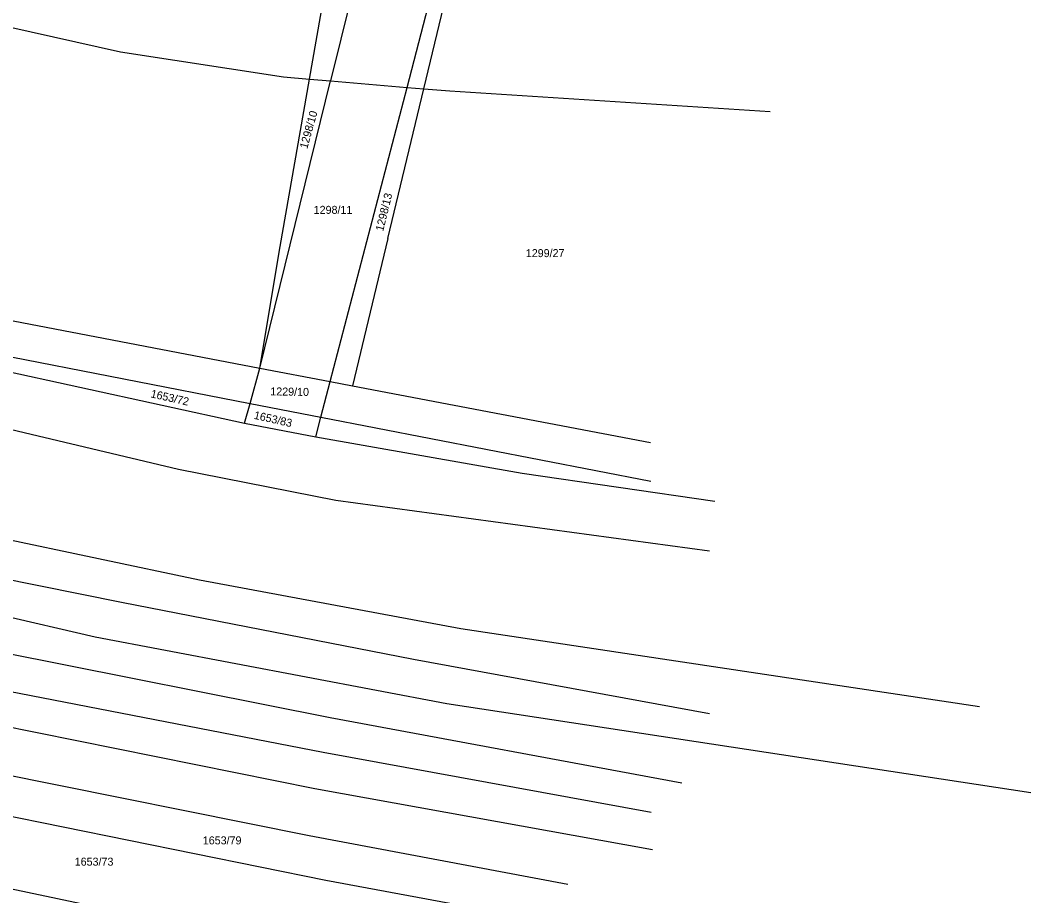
# Model space of a CAD drawing. Extents: x -563148 to -561712, y -1182311 to -1179502.
# Drawn here: x -561979.9 to -561790.5, y -1181327.8 to -1181163.6 of the extents above; entities that cross this region are included whole.
import ezdxf

# ---------------------------------------------------------------- set-up
doc = ezdxf.new("R2010")
doc.units = 0
doc.layers.add('Vrstva 55', color=7, linetype='Continuous')
doc.layers.add('Vrstva 57', color=7, linetype='Continuous')

msp = doc.modelspace()

# ---------------------------------------------------------------- linework, layer by layer
at = {"layer": 'Vrstva 55'}
for p, q in [((-561910.28, -1181129.09), (-561921.71, -1181175.02)), ((-561907.36, -1181176.23), (-561895.44, -1181130.59)), ((-561925.64, -1181174.69), (-561918.1, -1181131.86)), ((-561904.23, -1181176.49), (-561899.45, -1181156.54)), ((-561982, -1181164.87), (-561961.08, -1181169.57)), ((-561961.08, -1181169.57), (-561930.49, -1181174.28)), ((-561930.49, -1181174.28), (-561925.64, -1181174.69)), ((-561934.93, -1181228.84), (-561921.71, -1181175.02)), ((-561931.16, -1181206.06), (-561925.64, -1181174.69)), ((-561925.64, -1181174.69), (-561921.71, -1181175.02)), ((-561921.75, -1181231.35), (-561907.36, -1181176.23)), ((-561921.71, -1181175.02), (-561907.36, -1181176.23)), ((-561910.96, -1181204.59), (-561904.23, -1181176.49)), ((-561907.36, -1181176.23), (-561904.23, -1181176.49)), ((-561904.23, -1181176.49), (-561899.37, -1181176.9)), ((-561899.37, -1181176.9), (-561839.3, -1181180.78)), ((-562070.46, -1181203), (-561934.93, -1181228.84)), ((-561910.96, -1181204.59), (-561917.56, -1181232.15)), ((-561934.93, -1181228.84), (-561931.16, -1181206.06)), ((-562038.6, -1181215.7), (-561936.78, -1181235.47)), ((-561998.99, -1181225.82), (-561937.81, -1181239.16)), ((-561936.78, -1181235.47), (-561934.93, -1181228.84)), ((-561934.93, -1181228.84), (-561921.75, -1181231.35)), ((-561923.5, -1181238.05), (-561921.75, -1181231.35)), ((-561921.75, -1181231.35), (-561917.56, -1181232.15)), ((-561917.56, -1181232.15), (-561861.73, -1181242.8)), ((-562010.77, -1181233.37), (-561950.22, -1181247.8)), ((-561937.81, -1181239.16), (-561936.78, -1181235.47)), ((-561936.78, -1181235.47), (-561923.5, -1181238.05)), ((-561924.47, -1181241.77), (-561923.5, -1181238.05)), ((-561923.5, -1181238.05), (-561861.68, -1181250.05)), ((-561937.81, -1181239.16), (-561924.47, -1181241.77)), ((-561924.47, -1181241.77), (-561885.77, -1181248.57)), ((-561950.22, -1181247.8), (-561920.72, -1181253.59)), ((-561885.77, -1181248.57), (-561849.69, -1181253.81)), ((-561920.72, -1181253.59), (-561850.67, -1181263.14)), ((-561946.28, -1181268.62), (-561990.57, -1181259.23)), ((-561965.82, -1181279.3), (-562035.64, -1181263.14)), ((-561960.87, -1181272.79), (-561993.17, -1181266.27)), ((-561897.3, -1181277.74), (-561946.28, -1181268.62)), ((-561906.16, -1181283.47), (-561960.87, -1181272.79)), ((-561800.12, -1181292.33), (-561897.3, -1181277.74)), ((-561899.91, -1181291.81), (-561965.82, -1181279.3)), ((-561921.79, -1181294.42), (-561983.27, -1181282.17)), ((-561924.66, -1181307.71), (-562040.85, -1181284.25)), ((-561850.67, -1181293.64), (-561906.16, -1181283.47)), ((-561923.09, -1181300.93), (-561981.97, -1181289.47)), ((-561790.48, -1181308.49), (-561899.91, -1181291.81)), ((-561925.7, -1181316.57), (-562032.78, -1181294.94)), ((-561855.88, -1181306.67), (-561921.79, -1181294.42)), ((-561861.61, -1181312.14), (-561923.09, -1181300.93)), ((-561922.57, -1181324.91), (-562024.18, -1181304.32)), ((-561861.35, -1181319.18), (-561924.66, -1181307.71)), ((-561877.24, -1181325.69), (-561925.7, -1181316.57)), ((-562028.07, -1181316.71), (-561921.79, -1181338.99)), ((-561860.57, -1181336.38), (-561922.57, -1181324.91))]:
    msp.add_line(p, q, dxfattribs=at)

# ---------------------------------------------------------------- texts
at = {"layer": 'Vrstva 57'}
for s, rotation, p in [('1298/10', 74.4122, (-561926.07, -1181187.85)), ('1298/13', 76.2358, (-561911.84, -1181203.3)), ('1653/72', 347.2817, (-561955.5, -1181234.32)), ('1229/10', 359.0411, (-561933, -1181233.96)), ('1653/83', 347.2142, (-561936.16, -1181238.34))]:
    msp.add_text(s, height=1.5, rotation=rotation, dxfattribs=at).set_placement(p)
for s, p in [('1298/11', (-561924.86, -1181199.94)), ('1299/27', (-561885.11, -1181208.05)), ('1653/79', (-561945.64, -1181318.14)), ('1653/73', (-561969.64, -1181322.13))]:
    msp.add_text(s, height=1.5, dxfattribs=at).set_placement(p)

doc.saveas('drawing.dxf')
